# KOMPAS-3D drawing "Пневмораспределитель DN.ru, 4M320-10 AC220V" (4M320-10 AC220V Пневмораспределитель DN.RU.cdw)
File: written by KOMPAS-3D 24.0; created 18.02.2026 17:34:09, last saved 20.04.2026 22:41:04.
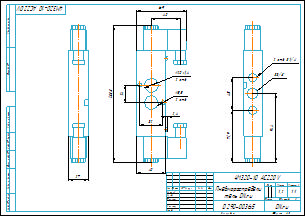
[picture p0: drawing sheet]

Document properties: Автор: R2D2; Форматы листов документа: A3; Полное имя файла: 4M320-10 AC220V Пневмораспределитель DN.RU.m3d; Масса: 1.2; Наименование: Пневмораспределитель DN.ru; Количество листов документа: 1; Примечание: D290-00365

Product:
- Part/product: Пневмораспределитель DN.ru  | designation 4M320-10 AC220V
    Масса: 1.2
    Раздел спецификации: Прочие изделия
    Примечание: D290-00365

Views: Вид 1, Спереди, Проекционный вид 2, Проекционный вид 3
Referenced files in E:\Работа\Зайцев\Аксессуары для пневмоприводов\Пневмораспределители DN.ru\4M320 AC220V Пневмораспределитель DN.RU\4M320-08 AC220V Пневмораспределитель DN.RU\: 4M320-08 AC220V 1-4' Пневмораспределитель DN.RU.m3d
Referenced files in E:\Работа\Зайцев\Аксессуары для пневмоприводов\Пневмораспределители DN.ru\4M320 AC220V Пневмораспределитель DN.RU\4M320-10 AC220V Пневмораспределитель DN.RU\: 4M320-10 AC220V Пневмораспределитель DN.RU.m3d
Referenced files in E:\Работа\Зайцев\Для компаса\: чертеж DN.ru А3.cdt
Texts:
  чертеж DN.ru А3.cdt
  Пневмораспредели
  тель DN.ru
  Пневмораспределитель DN.ru
  4M320-10 AC220V Пневмораспределитель DN.ru
Dimensions and other numbers on the sheet: 0; 3; 2; 4; 71,9; 45; 94,4; 2 отв. G1/4'; 4M320-10 AC220V; 5; 69; 40; 32; 24; 188,8; 2,4; 5,5; 2 отв.; 20; 6; 27; 1:1; 1; 1,2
